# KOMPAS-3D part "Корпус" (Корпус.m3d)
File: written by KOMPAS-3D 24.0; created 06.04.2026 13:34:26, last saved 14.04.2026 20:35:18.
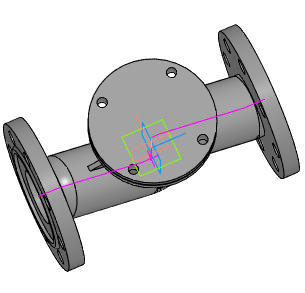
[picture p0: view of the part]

Document properties: Автор: R2D2; Полное имя файла: E:\Работа\Зайцев\VSO3131M-F-S Клапан запорный DN.ru Ду15-100 Ру40\DN65\исходные материалы\Корпус.m3d

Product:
- Body: Труба / Нестандартная труба / L = 148.6 мм  | qty 1
    Материал: Нестандартная труба (density 7856 kg/m3)
    Масса: 21.611311
    Раздел спецификации: Детали
    Примечание: 5,16 кг
    additional columns: Pipeline; 0.075; 0; 0; 0.002; 0.14858; true; 0.04
- Body: Труба / Нестандартная труба / L = 190 мм  | qty 1
    Материал: Нестандартная труба (density 7856 kg/m3)
    Масса: 21.611311
    Раздел спецификации: Детали
    Примечание: 6,59 кг
    additional columns: Pipeline; 0.075; 0; 0; 0.002; 0.18995; true; 0.04
- Body: Тело 4  | qty 1
    Материал: Нестандартная труба (density 7856 kg/m3)
    Масса: 21.611311
- Body: Тело 5  | qty 1
    Материал: Нестандартная труба (density 7856 kg/m3)
    Масса: 21.611311
- Body: Тело 8  | qty 1
    Материал: Нестандартная труба (density 7856 kg/m3)
    Масса: 21.611311
- Body: Тело 9  | qty 1
    Материал: Нестандартная труба (density 7856 kg/m3)
    Масса: 21.611311
- Part/product: Корпус
    Масса: 6.9

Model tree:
1. Труба
2. Труба:1  (labels: {F703FF30-5BE6-4673-A7F1-8EDA1BE1E2D1}; SHAPEOBJECT3D_ATTR_BUTT; SHAPEOBJECT3D_ATTR_VALID; SHAPEOBJECT3D_ATTR_BUTT_AREA)
     PIPE_R = 7
3. Труба:2  (labels: {F703FF30-5BE6-4673-A7F1-8EDA1BE1E2D1}; SHAPEOBJECT3D_ATTR_BUTT; SHAPEOBJECT3D_ATTR_VALID; SHAPEOBJECT3D_ATTR_BUTT_AREA)
     PIPE_R = 5
4. Колонна
5. Элемент выдавливания:1
     Смещение 1 = -1; Смещение 2 = -5
6. Скругление:17  (with: Ребро.Элемент выдавливания:1)
     Радиус = 1
7. Скругление:18  (with: Ребро.Элемент выдавливания:1)
8. Скругление:24  (with: Ребро.Элемент выдавливания:1)
     Радиус = 0.5
9. Элемент выдавливания:2
     Расстояние 1 = 6
10. Скругление:19  (with: Ребро.Элемент выдавливания:2)
     Радиус = 2
11. Эскиз:4  (with: Грань.Элемент выдавливания:1)
12. Элемент выдавливания:3
     Расстояние 1 = 17.5
13. Скругление:21  (with: Ребро.Элемент выдавливания:3)
14. ОТЛИВКА
15. Скругление:6  (with: Грань.Элемент выдавливания:1)
     Радиус = 2
16. Элемент выдавливания:6  (with: Грань.Элемент выдавливания:1)
     Смещение 1 = 4
17. ЛЕЙБЛ
18. Элемент выдавливания:7  (with: Грань.Элемент выдавливания:1)
     Расстояние 1 = 43.4996; Смещение 1 = 1
19. Фланец верх  (with: Ребро.Элемент выдавливания:3)
20. Элемент вращения:2
     Угол 1 = 360
21. Эскиз:12  (with: Грань.Элемент вращения:2)
22. Элемент выдавливания:9  (with: Грань.Элемент вращения:2)
     Расстояние 2 = 20
23. Массив по концентрической сетке:1  (with: Элемент выдавливания:9, Эскиз:12, Грань.Элемент вращения:2)  (4 pattern instances)
     Шаг 2 = 360
24. Фланец
25. Элемент вращения:1
     Угол 1 = 360
26. отвертие во фланце  (with: Грань.Элемент вращения:1)
27. Элемент выдавливания:8
28. Массив по концентрической сетке:2  (with: Элемент выдавливания:8, Эскиз:10, Грань.Элемент вращения:1)  (8 pattern instances)
     Шаг 2 = 360
29. Зеркальный массив:1
30. Экземпляр ( 1 )
31. Экземпляр ( 2 )  (with: Элемент вращения:1, Массив по концентрической сетке:2, Экземпляр ( 1 ), Элемент выдавливания:8)
32. Экземпляр ( 3 )  (with: Элемент выдавливания:8)
33. Экземпляр ( 4 )  (with: Элемент выдавливания:8)
34. Экземпляр ( 5 )  (with: Элемент выдавливания:8)
35. Экземпляр ( 6 )  (with: Элемент выдавливания:8)
36. Экземпляр ( 7 )  (with: Элемент выдавливания:8)
37. Экземпляр ( 8 )  (with: Элемент выдавливания:8)
38. Скругление:25  (with: Ребро.Элемент вращения:2)
     Радиус = 2
39. Скругление:26
     Радиус = 2

Expressions: DS/2+3; D1/2; DN/2; D/2; DS-v977*4; LL/2; D1-v1234*2
Referenced files in C:\Program Files\ASCON\KOMPAS-3D v24\Libs\Pipeline\: StylesTemplate.a3d, TemplateHPH, InsulationStylesTemplate.a3d, Insulation
Referenced files in C:\Program Files\ASCON\KOMPAS-3D v24\Templates\: Констр. чертеж А3 гориз. перв. лист.cdt
Referenced files in E:\Работа\Зайцев\VSO3131M-F-S Клапан запорный DN.ru Ду15-100 Ру40\DN20\исходные материалы\: 
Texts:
  Отводы ГОСТ 17375-2001
  Констр. чертеж А3 гориз. перв. лист.cdt
  GOST 26.020 Pr3
  var3D
  смещение колонны вниз
  LL-10
  DN+10
  Труба / Нестандартная труба / L = %s мм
